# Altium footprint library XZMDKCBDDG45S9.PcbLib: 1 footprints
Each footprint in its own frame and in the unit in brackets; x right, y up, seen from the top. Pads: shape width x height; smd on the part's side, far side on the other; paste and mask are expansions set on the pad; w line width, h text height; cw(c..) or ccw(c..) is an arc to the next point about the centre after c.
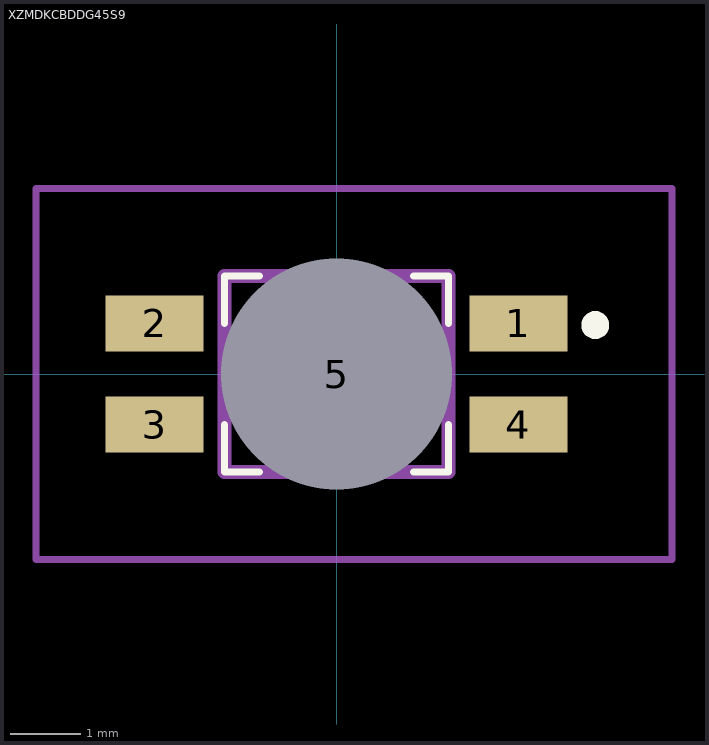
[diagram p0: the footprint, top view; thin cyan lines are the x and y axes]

## XZMDKCBDDG45S9 [mm]
pads (5):
  rect 1.4x0.8 smd: 1(2.6,0.725) 2(-2.6,0.725) 3(-2.6,-0.725) 4(2.6,-0.725)
  round 1.65 hole 3.3 unplated: 5(0,0)
Top Overlay:
  lines w0.1: -1.6,-0.725 -1.6,-1.4 -1.1,-1.4 ; -1.6,0.725 -1.6,1.4 -1.1,1.4 ; 1.1,-1.4 1.6,-1.4 1.6,-0.725 ; 1.1,1.4 1.6,1.4 1.6,0.725
  lines w0.2: 3.7,0.6 ccw(c3.7,0.7) 3.7,0.8 ; 3.7,0.6 3.7,0.6 ; 3.7,0.6 cw(c3.7,0.7) 3.7,0.8 ; 3.7,0.8 3.7,0.8
Mechanical 15:
  lines w0.2: -1.6,-1.4 1.6,-1.4 1.6,1.4 -1.6,1.4 -1.6,-1.4
Mechanical 20:
  lines w0.1: -4.3,-2.65 4.8,-2.65 4.8,2.65 -4.3,2.65 -4.3,-2.65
